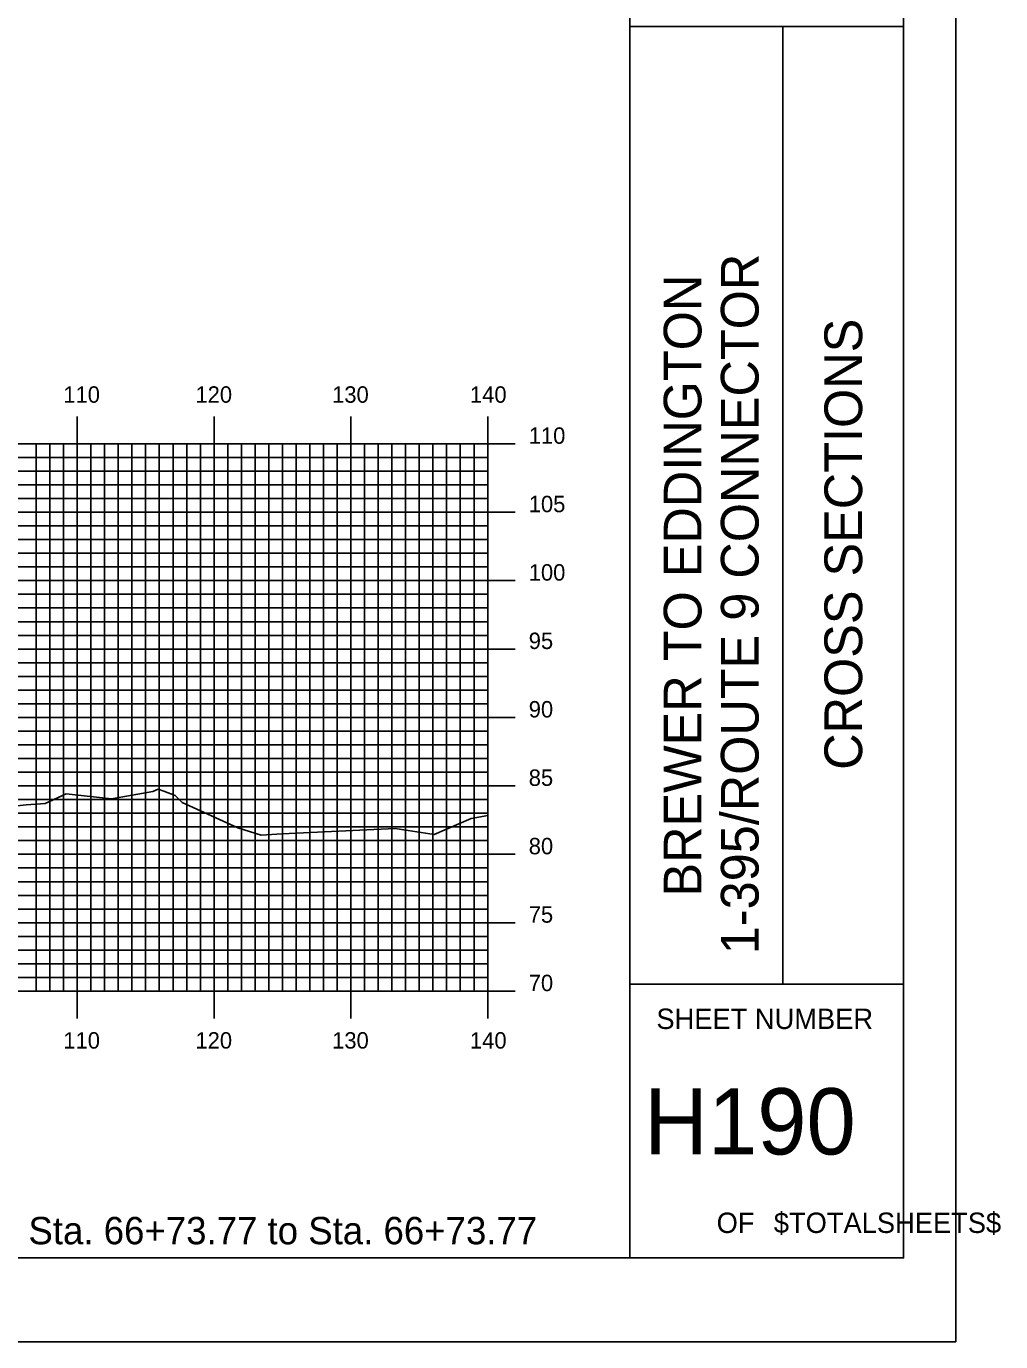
# Model space of a CAD drawing. Extents: x 1758647 to 1758990, y 442323 to 442543.
# Drawn here: x 1758918.7 to 1758989.9, y 442323.3 to 442419.4 of the extents above; entities that cross this region are included whole.
import ezdxf

# ---------------------------------------------------------------- set-up
doc = ezdxf.new("R2010")
doc.units = 0
for name, color, linetype in [('BORDER', 7, 'Continuous'), ('H_V ANNOTATION', 7, 'Continuous'), ('MAJOR', 7, 'Continuous'), ('MINOR', 7, 'Continuous'), ('PLOT BOUNDARY', 7, 'Continuous'), ('S_Roadway_Centerline', 7, 'Continuous')]:
    doc.layers.add(name, color=color, linetype=linetype)

msp = doc.modelspace()

# ---------------------------------------------------------------- linework, layer by layer
at = {"layer": 'BORDER'}
for p, q in [((1758962.822, 442329.386), (1758962.822, 442539.386)), ((1758962.822, 442419.392), (1758982.822, 442419.392)), ((1758974.004, 442349.392), (1758974.004, 442419.392)), ((1758962.822, 442349.392), (1758982.822, 442349.392))]:
    msp.add_line(p, q, dxfattribs=at)
msp.add_lwpolyline([(1758662.822, 442329.386), (1758982.822, 442329.386), (1758982.822, 442539.386), (1758662.822, 442539.386)], close=True, dxfattribs=at)
at = {"layer": 'MAJOR'}
for p, q in [((1758922.422, 442390.89), (1758922.422, 442388.886)), ((1758932.422, 442390.89), (1758932.422, 442388.886)), ((1758942.422, 442390.89), (1758942.422, 442388.886)), ((1758952.422, 442390.89), (1758952.422, 442388.886)), ((1758672.422, 442388.886), (1758952.422, 442388.886)), ((1758672.422, 442388.886), (1758952.422, 442388.886)), ((1758922.422, 442348.886), (1758922.422, 442388.886)), ((1758932.422, 442348.886), (1758932.422, 442388.886)), ((1758942.422, 442348.886), (1758942.422, 442388.886)), ((1758954.426, 442388.886), (1758950.418, 442388.886)), ((1758952.422, 442348.886), (1758952.422, 442388.886)), ((1758952.422, 442348.886), (1758952.422, 442388.886)), ((1758672.422, 442383.886), (1758952.422, 442383.886)), ((1758954.426, 442383.886), (1758950.418, 442383.886)), ((1758672.422, 442378.886), (1758952.422, 442378.886)), ((1758954.426, 442378.886), (1758950.418, 442378.886)), ((1758672.422, 442373.886), (1758952.422, 442373.886)), ((1758954.426, 442373.886), (1758950.418, 442373.886)), ((1758672.422, 442368.886), (1758952.422, 442368.886)), ((1758954.426, 442368.886), (1758950.418, 442368.886)), ((1758672.422, 442363.886), (1758952.422, 442363.886)), ((1758954.426, 442363.886), (1758950.418, 442363.886)), ((1758672.422, 442358.886), (1758952.422, 442358.886)), ((1758954.426, 442358.886), (1758950.418, 442358.886)), ((1758672.422, 442353.886), (1758952.422, 442353.886)), ((1758954.426, 442353.886), (1758950.418, 442353.886)), ((1758672.422, 442348.886), (1758952.422, 442348.886)), ((1758672.422, 442348.886), (1758952.422, 442348.886)), ((1758922.422, 442346.882), (1758922.422, 442348.886)), ((1758932.422, 442346.882), (1758932.422, 442348.886)), ((1758942.422, 442346.882), (1758942.422, 442348.886)), ((1758954.426, 442348.886), (1758950.418, 442348.886)), ((1758952.422, 442346.882), (1758952.422, 442348.886))]:
    msp.add_line(p, q, dxfattribs=at)
at = {"layer": 'MINOR'}
for p, q in [((1758919.422, 442348.886), (1758919.422, 442388.886)), ((1758920.422, 442348.886), (1758920.422, 442388.886)), ((1758921.422, 442348.886), (1758921.422, 442388.886)), ((1758923.422, 442348.886), (1758923.422, 442388.886)), ((1758924.422, 442348.886), (1758924.422, 442388.886)), ((1758925.422, 442348.886), (1758925.422, 442388.886)), ((1758926.422, 442348.886), (1758926.422, 442388.886)), ((1758927.422, 442348.886), (1758927.422, 442388.886)), ((1758928.422, 442348.886), (1758928.422, 442388.886)), ((1758929.422, 442348.886), (1758929.422, 442388.886)), ((1758930.422, 442348.886), (1758930.422, 442388.886)), ((1758931.422, 442348.886), (1758931.422, 442388.886)), ((1758933.422, 442348.886), (1758933.422, 442388.886)), ((1758934.422, 442348.886), (1758934.422, 442388.886)), ((1758935.422, 442348.886), (1758935.422, 442388.886)), ((1758936.422, 442348.886), (1758936.422, 442388.886)), ((1758937.422, 442348.886), (1758937.422, 442388.886)), ((1758938.422, 442348.886), (1758938.422, 442388.886)), ((1758939.422, 442348.886), (1758939.422, 442388.886)), ((1758940.422, 442348.886), (1758940.422, 442388.886)), ((1758941.422, 442348.886), (1758941.422, 442388.886)), ((1758943.422, 442348.886), (1758943.422, 442388.886)), ((1758944.422, 442348.886), (1758944.422, 442388.886)), ((1758945.422, 442348.886), (1758945.422, 442388.886)), ((1758946.422, 442348.886), (1758946.422, 442388.886)), ((1758947.422, 442348.886), (1758947.422, 442388.886)), ((1758948.422, 442348.886), (1758948.422, 442388.886)), ((1758949.422, 442348.886), (1758949.422, 442388.886)), ((1758950.422, 442348.886), (1758950.422, 442388.886)), ((1758951.422, 442348.886), (1758951.422, 442388.886)), ((1758672.422, 442387.886), (1758952.422, 442387.886)), ((1758952.422, 442387.886), (1758950.418, 442387.886)), ((1758672.422, 442386.886), (1758952.422, 442386.886)), ((1758952.422, 442386.886), (1758950.418, 442386.886)), ((1758672.422, 442385.886), (1758952.422, 442385.886)), ((1758952.422, 442385.886), (1758950.418, 442385.886)), ((1758672.422, 442384.886), (1758952.422, 442384.886)), ((1758952.422, 442384.886), (1758950.418, 442384.886)), ((1758672.422, 442382.886), (1758952.422, 442382.886)), ((1758952.422, 442382.886), (1758950.418, 442382.886)), ((1758672.422, 442381.886), (1758952.422, 442381.886)), ((1758952.422, 442381.886), (1758950.418, 442381.886)), ((1758672.422, 442380.886), (1758952.422, 442380.886)), ((1758952.422, 442380.886), (1758950.418, 442380.886)), ((1758672.422, 442379.886), (1758952.422, 442379.886)), ((1758952.422, 442379.886), (1758950.418, 442379.886)), ((1758672.422, 442377.886), (1758952.422, 442377.886)), ((1758952.422, 442377.886), (1758950.418, 442377.886)), ((1758672.422, 442376.886), (1758952.422, 442376.886)), ((1758952.422, 442376.886), (1758950.418, 442376.886)), ((1758672.422, 442375.886), (1758952.422, 442375.886)), ((1758952.422, 442375.886), (1758950.418, 442375.886)), ((1758672.422, 442374.886), (1758952.422, 442374.886)), ((1758952.422, 442374.886), (1758950.418, 442374.886)), ((1758672.422, 442372.886), (1758952.422, 442372.886)), ((1758952.422, 442372.886), (1758950.418, 442372.886)), ((1758672.422, 442371.886), (1758952.422, 442371.886)), ((1758952.422, 442371.886), (1758950.418, 442371.886)), ((1758672.422, 442370.886), (1758952.422, 442370.886)), ((1758952.422, 442370.886), (1758950.418, 442370.886)), ((1758672.422, 442369.886), (1758952.422, 442369.886)), ((1758952.422, 442369.886), (1758950.418, 442369.886)), ((1758672.422, 442367.886), (1758952.422, 442367.886)), ((1758952.422, 442367.886), (1758950.418, 442367.886)), ((1758672.422, 442366.886), (1758952.422, 442366.886)), ((1758952.422, 442366.886), (1758950.418, 442366.886)), ((1758672.422, 442365.886), (1758952.422, 442365.886)), ((1758952.422, 442365.886), (1758950.418, 442365.886)), ((1758672.422, 442364.886), (1758952.422, 442364.886)), ((1758952.422, 442364.886), (1758950.418, 442364.886)), ((1758672.422, 442362.886), (1758952.422, 442362.886)), ((1758952.422, 442362.886), (1758950.418, 442362.886)), ((1758672.422, 442361.886), (1758952.422, 442361.886)), ((1758952.422, 442361.886), (1758950.418, 442361.886)), ((1758672.422, 442360.886), (1758952.422, 442360.886)), ((1758952.422, 442360.886), (1758950.418, 442360.886)), ((1758672.422, 442359.886), (1758952.422, 442359.886)), ((1758952.422, 442359.886), (1758950.418, 442359.886)), ((1758672.422, 442357.886), (1758952.422, 442357.886)), ((1758952.422, 442357.886), (1758950.418, 442357.886)), ((1758672.422, 442356.886), (1758952.422, 442356.886)), ((1758952.422, 442356.886), (1758950.418, 442356.886)), ((1758672.422, 442355.886), (1758952.422, 442355.886)), ((1758952.422, 442355.886), (1758950.418, 442355.886)), ((1758672.422, 442354.886), (1758952.422, 442354.886)), ((1758952.422, 442354.886), (1758950.418, 442354.886)), ((1758672.422, 442352.886), (1758952.422, 442352.886)), ((1758952.422, 442352.886), (1758950.418, 442352.886)), ((1758672.422, 442351.886), (1758952.422, 442351.886)), ((1758952.422, 442351.886), (1758950.418, 442351.886)), ((1758672.422, 442350.886), (1758952.422, 442350.886)), ((1758952.422, 442350.886), (1758950.418, 442350.886)), ((1758672.422, 442349.886), (1758952.422, 442349.886)), ((1758952.422, 442349.886), (1758950.418, 442349.886))]:
    msp.add_line(p, q, dxfattribs=at)
at = {"layer": 'PLOT BOUNDARY'}
msp.add_lwpolyline([(1758646.635, 442323.268), (1758986.635, 442323.268), (1758986.635, 442543.268), (1758646.635, 442543.268)], close=True, dxfattribs=at)
at = {"layer": 'S_Roadway_Centerline'}
msp.add_lwpolyline([(1758867.097, 442362.07), (1758890.019, 442361.397), (1758890.051, 442361.402), (1758890.159, 442361.42), (1758897.211, 442362.426), (1758908.393, 442361.555), (1758909.905, 442361.54), (1758918.679, 442362.511), (1758920.08, 442362.587), (1758921.604, 442363.303), (1758924.916, 442362.945), (1758927.947, 442363.487), (1758928.339, 442363.643), (1758928.755, 442363.497), (1758929.584, 442363.173), (1758930.099, 442362.672), (1758934.156, 442360.81), (1758935.874, 442360.286), (1758937.404, 442360.383), (1758945.665, 442360.765), (1758948.51, 442360.338), (1758951.206, 442361.509), (1758952.422, 442361.728)], dxfattribs=at)

# ---------------------------------------------------------------- texts
at = {"layer": 'BORDER'}
for s, p in [('1-395/ROUTE 9 CONNECTOR', (1758972.224, 442351.586)), ('BREWER TO EDDINGTON', (1758968.045, 442355.795)), ('CROSS SECTIONS', (1758979.791, 442365.06))]:
    msp.add_text(s, height=2.75575, rotation=90, dxfattribs=at).set_placement(p)
for s, height, p in [('SHEET NUMBER', 1.49054, (1758964.753, 442346.119)), ('H190', 4.8388, (1758963.853, 442336.951)), ('OF', 1.4905, (1758969.156, 442331.212)), ('$TOTALSHEETS$', 1.49054, (1758973.335, 442331.212))]:
    msp.add_text(s, height=height, dxfattribs=at).set_placement(p)
at = {"layer": 'H_V ANNOTATION'}
for s, height, p in [('110', 1.2, (1758921.405, 442391.886)), ('120', 1.2, (1758931.062, 442391.886)), ('130', 1.2, (1758941.052, 442391.886)), ('140', 1.2, (1758951.127, 442391.886)), ('110', 1.2, (1758955.422, 442388.886)), ('105', 1.2, (1758955.422, 442383.886)), ('100', 1.2, (1758955.422, 442378.886)), ('95', 1.2, (1758955.422, 442373.886)), ('90', 1.2, (1758955.422, 442368.886)), ('85', 1.2, (1758955.422, 442363.886)), ('80', 1.2, (1758955.422, 442358.886)), ('75', 1.2, (1758955.422, 442353.886)), ('70', 1.2, (1758955.422, 442348.886)), ('110', 1.2, (1758921.405, 442344.686)), ('120', 1.2, (1758931.062, 442344.686)), ('130', 1.2, (1758941.052, 442344.686)), ('140', 1.2, (1758951.127, 442344.686)), ('Sta. 66+73.77 to Sta. 66+73.77', 2.0004, (1758918.855, 442330.386))]:
    msp.add_text(s, height=height, dxfattribs=at).set_placement(p)

doc.saveas('drawing.dxf')
